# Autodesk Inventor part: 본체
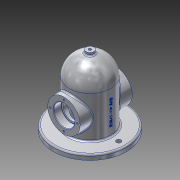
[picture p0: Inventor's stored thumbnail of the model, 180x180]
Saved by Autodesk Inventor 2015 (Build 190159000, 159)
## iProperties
Created: 2019-11
Part Number: 본체
Material: 알루미늄 6061
Document SubType Name: Modeling
Designer: LINEART-SSD.D4.16.07
Density: 2.7 g/cm^3
Appearance: 알루미늄 - 평지
Mass: 1105.87 g
Surface Area: 883.823 cm^2
Volume: 409.58 cm^3
Author: LINEART-SSD.D4.16.07
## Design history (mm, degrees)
sketch "스케치1"
  geometry: C1 r 70 at (0, 0); 1 further point
  constraints: 1 centre point, 1 coincident
  dimensions: "d0" = 140 diameter of C1
extrude "돌출1" new body sketch "스케치1" distance "d1" = 10; taper "d2" = 0 deg
sketch "스케치2"
  geometry: C1 r 70 at (0, 0) reference; C2 r 40 at (0, 0); 1 further point
  constraints: 1 centre point, 1 coincident
  dimensions: "d3" = 80 diameter of C2
extrude "돌출2" join sketch "스케치2" distance "d4" = 80; taper "d5" = 0 deg
sketch "스케치3"
  geometry: L1 (40, 90)-(-40, 90) reference; L2 (-40, 10)-(40, 10) reference; L3 (0, 90)-(0, 130); L4 (0, 90)-(-40, 90); L5 (40, 90)-(-40, 90) reference; A1 r 40 centre (0, 90) between (0, 130) and (-40, 90); 1 further point
  constraints: 6 end point, 2 point on circle, 1 centre point, 1 collinear, 1 midpoint
  dimensions: "d7" = 90 deg angle of L3 L1
revolve "회전1" sketch "스케치3" stored, may be unused: angle "d8" = 90 deg
node "작업 평면1"
sketch "스케치4"
  geometry: L1 (0, 0)-(0, 50); C1 r 31 at (0, 50)
  constraints: 2 end point, 1 centre point, 1 coincident, 1 vertical
  dimensions: "d10" = 50 distance of L1.start L1.end; "d11" = 62 diameter of C1
extrude "돌출3" join sketch "스케치4" stored distance "d12" = 80; taper "d13" = 0 deg
node "작업 평면2"
sketch "스케치5"
  geometry: L1 (0, 0)-(0, 50); C1 r 31 at (0, 50)
  constraints: 2 end point, 1 centre point, 1 coincident, 1 vertical
  dimensions: "d15" = 50 distance of L1.start L1.end; "d16" = 62 diameter of C1
extrude "돌출4" join sketch "스케치5" stored distance "d17" = 80; taper "d18" = 0 deg
sketch "스케치6"
  geometry: C1 r 31 at (0, 0) reference; A1 r 26 centre (0, 0) between (0, -26) and (26, 0); 3 further points
  constraints: 4 point on circle, 1 centre point, 1 coincident
  dimensions: "d19" = 52 diameter of A1; "d20" = 36.76955 distance of point (-26, 0) A1.start; "d21" = 36.76955 distance of point (-26, 0) point (0, 26); "d22" = 36.76955 distance of point (0, 26) A1.end; "d23" = 26 horizontal distance of A1.end A1.start
hole "구멍1" sketch "스케치6" at (0, -26), (26, 0), (0, 26), (-26, 0) diameter "d24" = 3.459; stored, may be unused: countersink angle "d28" = 90 deg, drill point angle "d30" = 118 deg; dims "d25" = 8, "d26" = 4, "d27" = 2, "d29" = 10
sketch "스케치7"
  geometry: C1 r 1.73 at (0, 26) reference; C2 r 1.73 at (0, -26) reference; C3 r 1.73 at (26, 0) reference; C4 r 1.73 at (-26, 0) reference; C5 r 31 at (0, 0) reference; C6 r 20 at (0, 0); 1 further point
  constraints: 1 centre point, 1 coincident
  dimensions: "d31" = 40 diameter of C6
extrude "돌출5" cut sketch "스케치7" distance "d32" = 15; taper "d33" = 0 deg
sketch "스케치8"
  geometry: C1 r 31 at (0, 0) reference; C2 r 16.5 at (0, 0); 1 further point
  constraints: 1 centre point, 1 coincident
  dimensions: "d34" = 33 diameter of C2
extrude "돌출6" cut sketch "스케치8" stored distance "d35" = 15; taper "d36" = 0 deg
sketch "스케치9"
  geometry: C1 r 16.5 at (0, 0) reference; C2 r 31 at (0, 0) reference; C3 r 1.73 at (0, 26) reference; C4 r 1.73 at (0, -26) reference; A1 r 26 centre (0, 0) between (-26, 0) and (26, 0); 3 further points
  constraints: 3 coincident, 2 point on circle, 1 centre point
  dimensions: "d37" = 52 diameter of A1; "d38" = 36.76955 distance of A1.end point (0, 26); "d39" = 36.76955 distance of A1.start point (0, -26)
hole "구멍2" sketch "스케치9" at (0, 26), (-26, 0), (0, -26), (26, 0) diameter "d40" = 3.459; stored, may be unused: countersink angle "d44" = 90 deg, drill point angle "d46" = 118 deg; dims "d41" = 8, "d42" = 4, "d43" = 2, "d45" = 10
sketch "스케치10"
  geometry: C1 r 20 at (0, 0) reference; C2 r 1.73 at (0, -26) reference; C3 r 1.73 at (0, 26) reference; C4 r 1.73 at (26, 0) reference; C5 r 1.73 at (-26, 0) reference; C6 r 31 at (0, 0) reference; C7 r 20 at (0, 0); 1 further point
  constraints: 1 centre point, 1 coincident
  dimensions: "d47" = 40 diameter of C7
extrude "돌출7" cut sketch "스케치10" distance "d48" = 15; taper "d49" = 0 deg
node "작업 평면3"
sketch "스케치11"
  geometry: C1 r 7.5 at (0, 0); 1 further point
  constraints: 1 centre point, 1 coincident
  dimensions: "d51" = 15 diameter of C1
extrude "돌출8" join sketch "스케치11" stored distance "d52" = 15; taper "d53" = 0 deg
sketch "스케치12"
  geometry: C1 r 7.5 at (0, 0) reference; 2 further points
  constraints: 1 coincident
hole "구멍3" sketch "스케치12" at (0, 0) diameter "d54" = 5.188; stored, may be unused: countersink angle "d58" = 90 deg, drill point angle "d60" = 118 deg; dims "d55" = 12, "d56" = 4, "d57" = 2, "d59" = 16
sketch "스케치13"
  geometry: C1 r 2.594 at (0, 0) reference; C2 r 70 at (0, 0) reference; C3 r 30 at (0, 0); 1 further point
  constraints: 1 centre point, 1 coincident
  dimensions: "d61" = 60 diameter of C3
extrude "돌출9" cut sketch "스케치13" distance "d62" = 90; taper "d63" = 0 deg
sketch "스케치14"
  geometry: L1 (-7.5, 129.291)-(7.5, 129.291) reference; L2 (40, 90)-(-40, 90) reference; L3 (0, 90)-(0, 120); L4 (0, 90)-(30, 90); A1 r 30 centre (0, 90) between (30, 90) and (0, 120); 1 further point
  constraints: 4 end point, 2 point on circle, 1 centre point, 1 collinear, 1 midpoint, 1 point on line
  dimensions: "d66" = 90 deg angle of L2 L3; "d67" = 30 radius of A1
revolve "회전2" sketch "스케치14" stored, may be unused: angle "d68" = 90 deg
sketch "스케치15"
  geometry: L1 (0, 0)-(-55, 0); L2 (0, 0)-(55, 0); C1 r 40 at (0, 0) reference; C2 r 70 at (0, 0) reference; C3 r 4.5 at (-55, 0); C4 r 4.5 at (55, 0); C5 r 2.594 at (0, 0) reference; A1 r 55 centre (0, 0) between (-55, 0) and (55, 0); 1 further point
  constraints: 4 end point, 3 centre point, 2 horizontal, 2 point on circle, 1 coincident
  dimensions: "d69" = 110 diameter of A1; "d70" = 9 diameter of C3; "d71" = 9 diameter of C4
extrude "돌출10" cut sketch "스케치15" stored distance "d72" = 90; taper "d73" = 0 deg
fillet "모깎기1" dims "d74" = 3
fillet "모깎기2" dims "d75" = 0.3
chamfer "모따기1" distance "d76" = 1; stored, may be unused: second distance "d77" = 2, angle "d78" = 45 deg
node "작업 평면4"
sketch "스케치17"
  geometry: L1 (0, 0)-(0, 50); 1 further point
  constraints: 2 end point, 1 coincident, 1 vertical, 1 other
  dimensions: "d83" = 50 distance of L1.start L1.end
feature "엠보싱2" sketch "스케치17" dims "d84" = 0.5, "d85" = 0
node "솔리드1"
node "투영된 루프1"
node "투영된 루프2"
node "투영된 루프3"
node "투영된 루프4"
node "투영된 루프5"
node "투영된 루프6"
node "투영된 루프7"
node "투영된 루프8"
node "투영된 루프9"
node "투영된 루프10"
node "투영된 루프11"
other parameters: "d50" = 135
